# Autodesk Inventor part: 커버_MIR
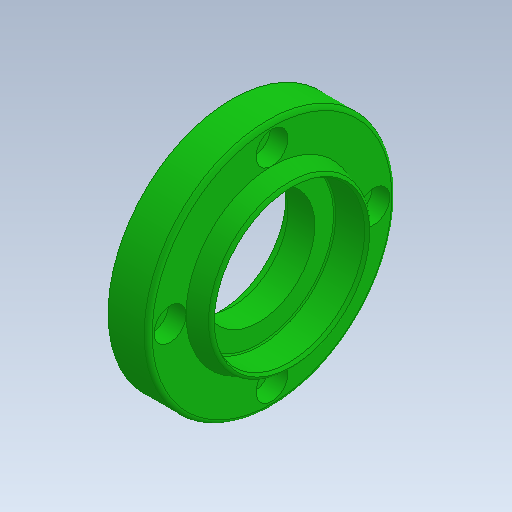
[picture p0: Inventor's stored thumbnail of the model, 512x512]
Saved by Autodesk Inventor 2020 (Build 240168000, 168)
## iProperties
Created: 2018-11
Part Number: 커버_MIR
Material: 알루미늄 6061
Document SubType Name: Modeling
Designer: Owner
Density: 2.71 g/cm^3
Appearance: 알루미늄 - 평지
Author: mduedu
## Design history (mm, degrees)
derived "커버.ipt"
  sketch "스케치1"
    geometry: L1 (0, 0)-(-3, 0) reference; L2 (-3, 0)-(-3, 20) reference; L3 (-3, 20)-(0, 20) reference; L4 (0, 20)-(0, 0) reference; L5 (-3, 0)-(-13, 0) reference; L6 (-13, 0)-(-13, 31) reference; L7 (-13, 31)-(-3, 31) reference; L8 (-3, 31)-(-3, 0) reference; L9 (-13, 0)-(-18, 0) reference; L10 (-18, 0)-(-18, 20) reference; L11 (-13, 15)-(-13, 0) reference; L12 (-18, 20)-(-13, 21.5) reference
  sketch "스케치2"
    geometry: L1 (0, -20)-(0, 20) reference; L2 (0, 20)-(-3, 20) reference; L3 (-3, 20)-(-3, 31) reference; L4 (-3, 31)-(-13, 31) reference; L5 (-13, 31)-(-13, 21.5) reference; L6 (-18, 20)-(-18, -20) reference; L7 (-13, -21.5)-(-13, -31) reference; L8 (-13, -31)-(-3, -31) reference; L9 (-3, -31)-(-3, -20) reference; L10 (-3, -20)-(0, -20) reference; L11 (0, 0)-(-3, 0) reference; L12 (-3, 0)-(-3, 16.5) reference; L13 (-3, 16.5)-(0, 16.5) reference; L14 (0, 16.5)-(0, 0) reference; L15 (-3, 0)-(-9.7, 0) reference; L16 (-9.7, 0)-(-9.7, 14) reference; L17 (-9.7, 14)-(-3, 14) reference; L18 (-3, 14)-(-3, 0) reference; L19 (-9.7, 0)-(-18, 0) reference; L20 (-18, 0)-(-18, 19) reference; L21 (-18, 19)-(-9.7, 19) reference; L22 (-9.7, 19)-(-9.7, 0) reference; L23 (-13, 21.5)-(-18, 20) reference; L24 (-18, -20)-(-13, -21.5) reference
  sketch "스케치3"
    geometry: 6 further points
    constraints: 1 vertical alignment, 1 other
  sketch "스케치4"
    geometry: C1 r 1.621 at (0, 25.5) reference; C2 r 1.621 at (-25.5, 0) reference; C3 r 1.621 at (0, -25.5) reference; C4 r 1.621 at (25.5, 0) reference
feature "솔리드1::커버.ipt"
tag "피쳐 태그1"
node "솔리드1"
